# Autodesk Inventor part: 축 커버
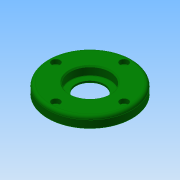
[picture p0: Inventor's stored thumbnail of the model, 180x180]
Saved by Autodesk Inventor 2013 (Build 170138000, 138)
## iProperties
Created: 2015-10
Part Number: 축 커버
Document SubType Name: Modeling
Designer: mdu
Density: 1 g/cm^3
Material: 알루미늄 6061
Mass: 40.8575 g
Surface Area: 133.807 cm^2
Volume: 40.8575 cm^3
Author: mdu
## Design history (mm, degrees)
sketch "스케치1"
  geometry: C1 r 40 at (0, 0) reference; C2 r 26 at (0, 0) reference; 1 further point
  node "참조1"
  node "참조2"
extrude "돌출1" new body sketch "스케치1" distance "d0" = 10; taper "d1" = 0 deg
extrude "돌출2" join sketch "스케치1" distance "d2" = 3; taper "d3" = 0 deg
hole "구멍1" diameter "d6" = 27; stored, may be unused: countersink angle "d10" = 90 deg, drill point angle "d12" = 118 deg; dims "d7" = 6, "d8" = 38, "d9" = 8.3, "d11" = 8, "d31" = 10, "d32" = 10
sketch "스케치2"
  geometry: C1 r 20 at (0, 0); 1 further point
  constraints: 1 centre point, 1 coincident
  dimensions: "d13" = 40 diameter of C1
extrude "돌출3" cut sketch "스케치2" distance "d14" = 3; taper "d15" = 0 deg
sketch "스케치3"
  geometry: C1 r 1.621 at (0, 32.5) reference; 1 further point
hole "구멍2" sketch "스케치3" at (0, 32.5) diameter "d16" = 4.5; stored, may be unused: countersink angle "d20" = 90 deg, drill point angle "d22" = 118 deg; dims "d17" = 6, "d18" = 8, "d19" = 4.4, "d21" = 8
fillet "모깎기1" dims "d26" = 3, "d27" = 0.3
chamfer "모따기1" distance "d28" = 1; stored, may be unused: second distance "d29" = 2, angle "d30" = 45 deg
node "솔리드1"
pattern_circular "원형 패턴1" dims angle "d24" = 360 deg
node "참조3"
